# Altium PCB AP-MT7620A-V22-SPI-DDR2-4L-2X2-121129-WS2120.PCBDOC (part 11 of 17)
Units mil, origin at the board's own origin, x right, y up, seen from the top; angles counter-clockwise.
Board outline 7316 x 4279 mil, 4 copper layers (Top, Inner Layer 2, Inner Layer 3, Bottom), stack 35.4 mil thick; 640 components, 473 nets, 2041 pads, 2358 vias.
Unrouted connection lines stored in the file: 11.
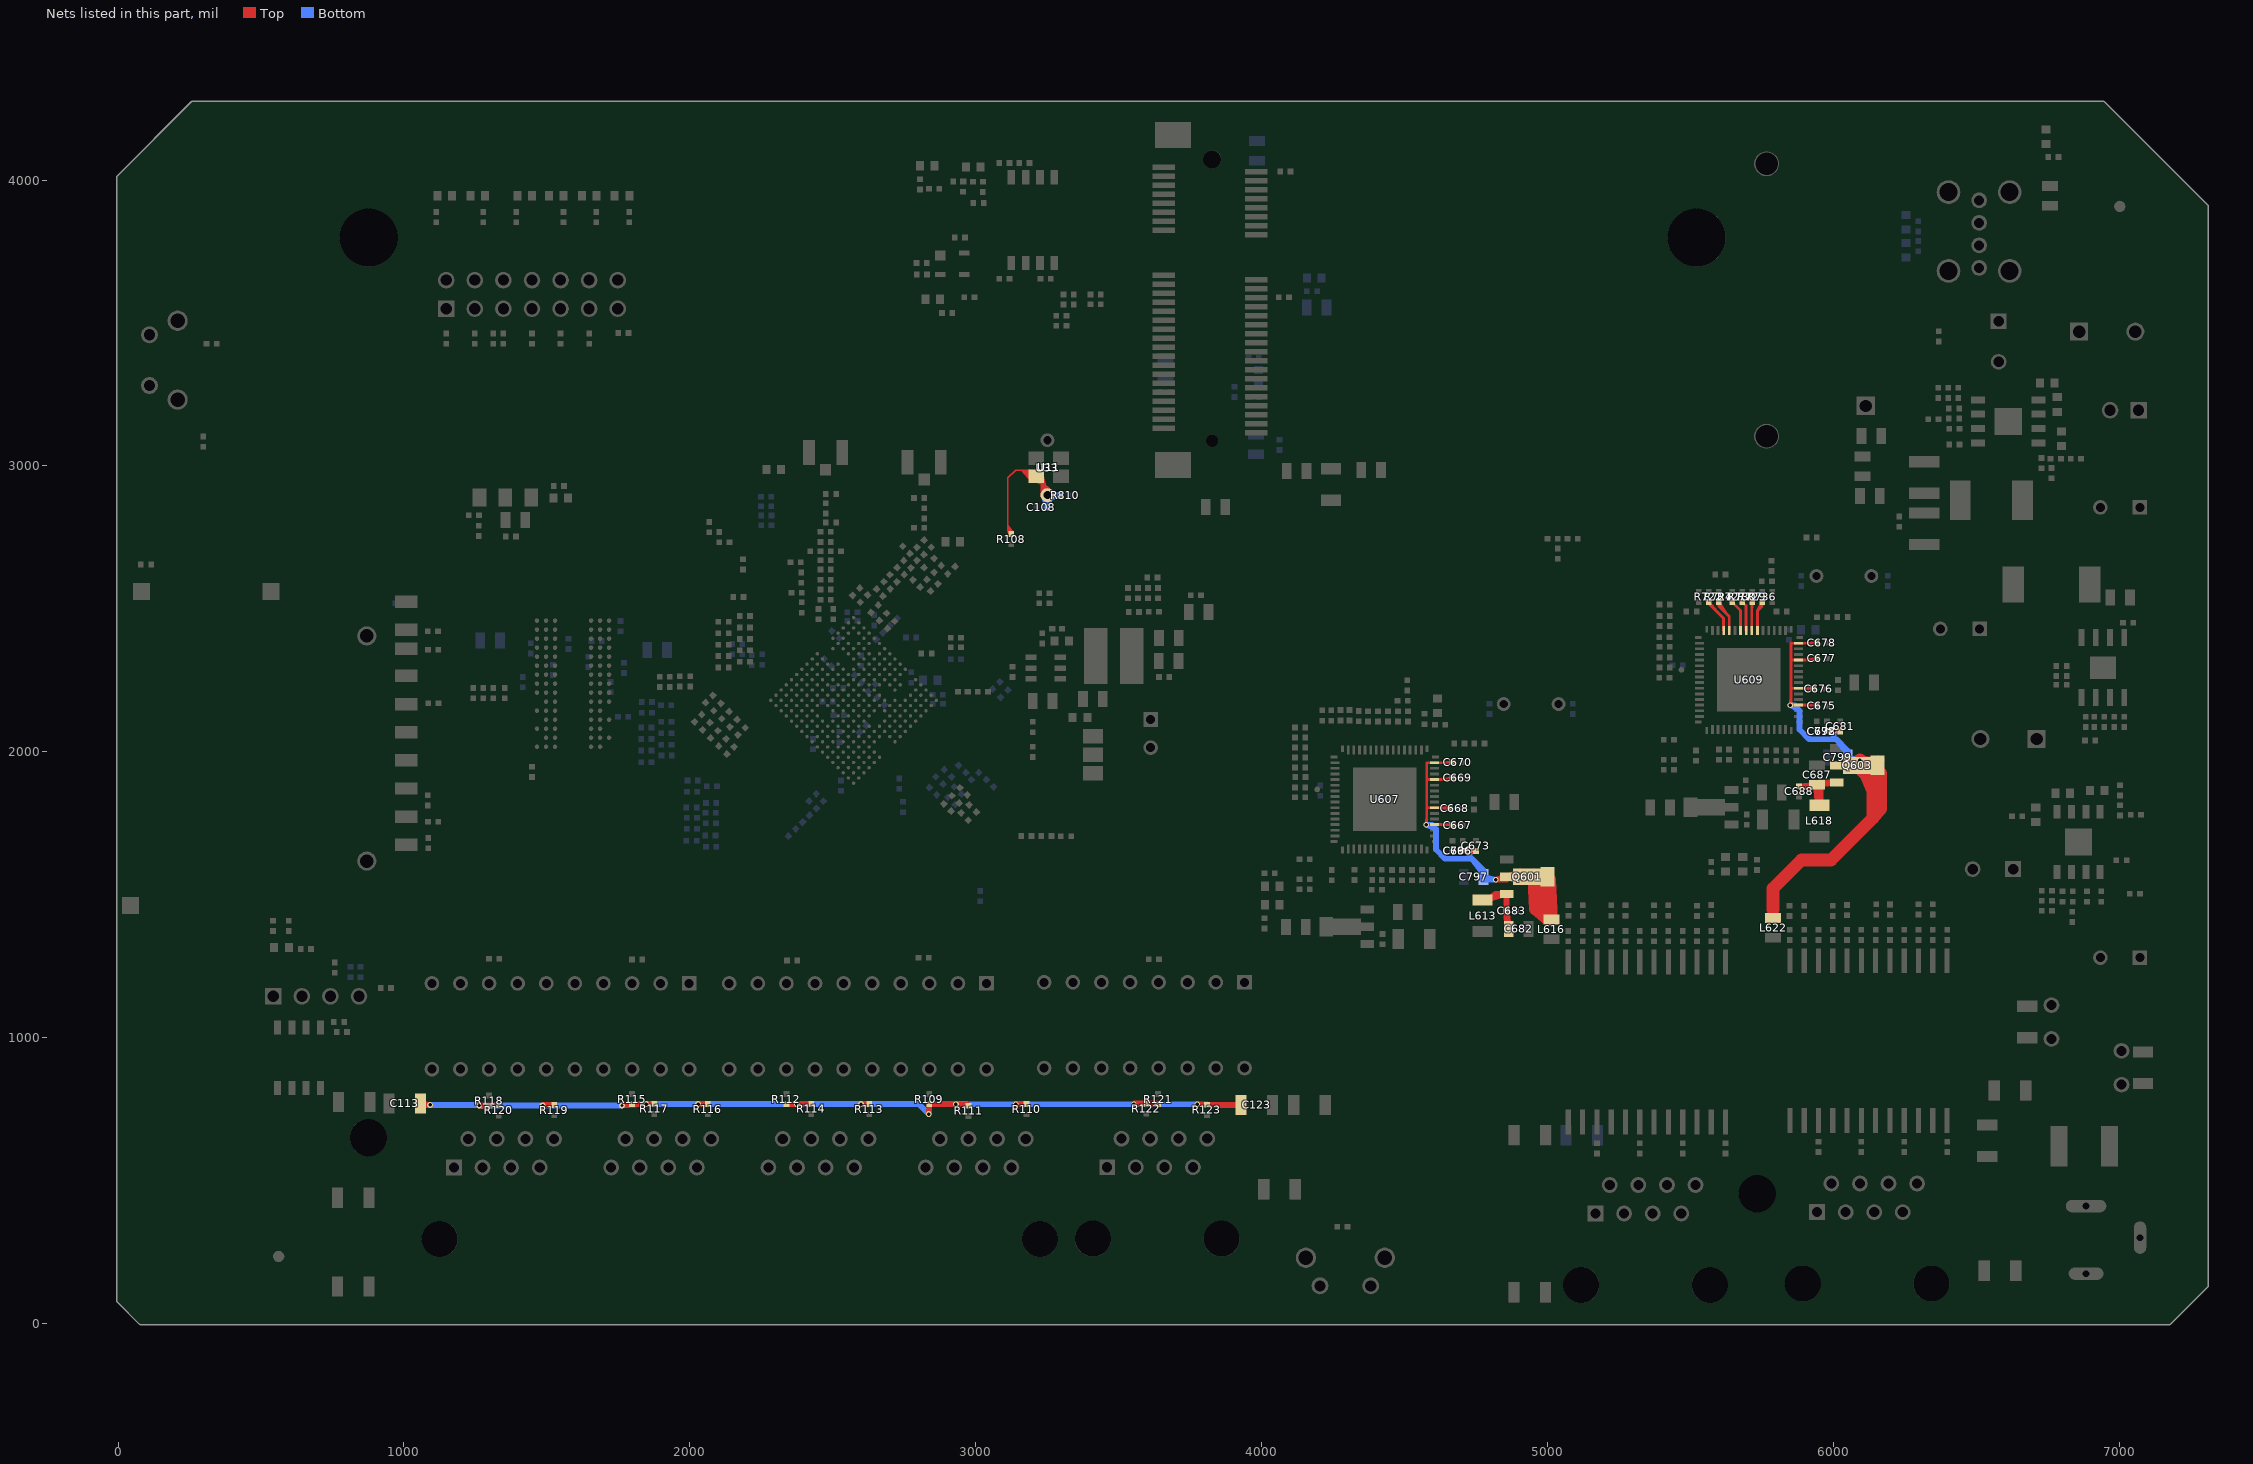
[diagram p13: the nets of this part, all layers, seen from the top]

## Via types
v1: diameter 20, hole 12, Top to Bottom, 2117 vias
v2: diameter 16, hole 8, Top to Bottom, 241 vias

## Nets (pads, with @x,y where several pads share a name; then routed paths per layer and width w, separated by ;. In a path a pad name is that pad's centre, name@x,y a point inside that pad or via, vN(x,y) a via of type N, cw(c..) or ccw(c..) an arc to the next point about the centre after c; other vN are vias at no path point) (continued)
OSC_O_1-CPU-RT0: C108.1 R108.2 R810.1 U11.1 U33.1 | length 5054.6
  Top w5: R108.2@3116.73,2760.14 3112.5,2791.8 ; R108.2@3130.63,2765.5 3112.5,2791.8 ; U11.1@3195.26,2946.47 3160.59,2985 ; U11.1@3198.87,2950.05 3160.59,2985 ; U11.1@3202.08,2953.94 3160.59,2985 ; U11.1@3203.47,2946.23 3245.92,2929.28 ; U11.1@3204.89,2958.09 3160.59,2985 ; U11.1@3205.63,2950.86 3245.92,2929.28 ; U11.1@3207.76,2963.5 3160.59,2985 ; U11.1@3208.26,2955.17 3245.92,2929.28 ; U11.1@3209.96,2969.21 3160.59,2985 ; U11.1@3211.26,2974.06 3160.59,2985 ; U11.1@3211.33,2959.15 3245.92,2929.28 ; U11.1@3212.08,2979.04 3160.59,2985 ; U11.1@3212.42,2984.11 3160.59,2985 ; U11.1@3215.63,2963.5 3245.92,2929.28 ; U11.1@3220.48,2967.25 3245.92,2929.28 ; U11.1@3224.79,2969.81 3245.92,2929.28 ; U11.1@3229.4,2971.89 3245.92,2929.28 ; U33.1@3229.75,2893.49 U11.1@3230.03,2945.17 ; U11.1@3234.25,2973.47 3245.92,2929.28 ; U33.1@3234.83,2893.71 U11.1@3230.03,2945.17 ; U33.1@3239.83,2894.43 U11.1@3230.03,2945.17 ; U33.1@3244.7,2895.62 U11.1@3230.03,2945.17 ; U33.1@3256.95,2901.05 U11.1@3230.03,2945.17 ; U33.1@3261.1,2903.87 U11.1@3230.03,2945.17 ; U33.1@3264.98,2907.1 U11.1@3230.03,2945.17 ; U33.1@3268.55,2910.72 U11.1@3230.03,2945.17 ; 3112.5,2773.5 3112.5,2958 3139.5,2985 3190.2,2985 U11.1@3211.69,2963.5 3251,2924.2 ; 3112.5,2773.5 R108.2@3124,2762 ; 3112.5,2773.5 3117.62,2758.06 3112.5,2773.5 ; 3112.5,2773.5 3127.94,2768.38 3112.5,2773.5 ; 3112.5,2773.5 R108.2@3124,2762 ; 3112.5,2791.8 R108.2@3124,2762 ; U11.1@3230.03,2945.17 U33.1@3251,2897.94 ; U33.1@3251,2897.94 3251,2924.2 ; U33.1@3251,2897.94 3251,2924.2 ; 3251,2924.2 3231.23,2906.91 3251,2924.2 ; 3251,2924.2 3270.77,2906.91 3251,2924.2 ; 3251,2924.2 3235.16,2903.26 3251,2924.2 ; 3251,2924.2 3266.84,2903.26 3251,2924.2 ; 3251,2924.2 3239.58,2900.55 3251,2924.2 ; 3251,2924.2 3262.42,2900.55 3251,2924.2 ; 3251,2924.2 3244.34,2898.79 3251,2924.2 ; 3251,2924.2 3257.66,2898.79 3251,2924.2
  Bottom w5: U33.1@3229.3,2897.19 C108.1@3241.48,2859.02 ; U33.1@3229.73,2893.56 C108.1@3248,2858.68 ; U33.1@3230.75,2890.1 C108.1@3254.94,2857.67 ; U33.1@3234.29,2898.43 C108.1@3241.48,2859.02 ; U33.1@3234.45,2895.64 C108.1@3248,2858.68 ; U33.1@3235.06,2892.91 C108.1@3254.94,2857.67 ; U33.1@3239.32,2897.08 C108.1@3248,2858.68 ; U33.1@3239.34,2899.03 C108.1@3241.48,2859.02 ; U33.1@3239.63,2895.12 C108.1@3254.94,2857.67 ; C108.1@3240.58,2856.12 3248,2880 C108.1@3255.42,2856.12 ; U33.1@3244.29,2897.88 C108.1@3248,2858.68 ; U33.1@3244.37,2898.98 C108.1@3241.48,2859.02 ; U33.1@3244.4,2896.73 C108.1@3254.94,2857.67 ; C108.1@3248,2855 3248,2894.94 U33.1@3251,2897.94 ; U33.1@3250.34,2891.26 R810.1@3290.78,2890.62 ; U33.1@3250.57,2886.23 R810.1@3290.78,2890.62 ; U33.1@3250.63,2904.64 R810.1@3290.63,2903.5 ; U33.1@3251.09,2909.65 R810.1@3290.63,2903.5 ; U33.1@3251.44,2881.23 R810.1@3290.78,2890.62 ; U33.1@3251.44,2891.24 R810.1@3290.22,2897.18 ; U33.1@3251.57,2891.25 R810.1@3290.21,2897.94 ; U33.1@3251.57,2904.62 R810.1@3290.21,2897.94 ; U33.1@3251.7,2904.61 R810.1@3290.22,2897.18 ; U33.1@3252.18,2914.61 R810.1@3290.63,2903.5 ; U33.1@3252.52,2886.32 R810.1@3290.22,2897.18 ; U33.1@3252.49,2891.39 R810.1@3290.63,2903.5 ; U33.1@3252.75,2886.36 R810.1@3290.21,2897.94 ; U33.1@3252.76,2904.42 R810.1@3290.78,2890.62 ; U33.1@3252.75,2909.52 R810.1@3290.21,2897.94 ; U33.1@3252.95,2876.31 R810.1@3290.78,2890.62 ; U33.1@3252.97,2909.48 R810.1@3290.22,2897.18 ; U33.1@3253.93,2919.45 R810.1@3290.63,2903.5 ; U33.1@3254.24,2881.54 R810.1@3290.22,2897.18 ; U33.1@3254.31,2886.7 R810.1@3290.63,2903.5 ; U33.1@3254.56,2881.61 R810.1@3290.21,2897.94 ; U33.1@3254.56,2914.27 R810.1@3290.21,2897.94 ; U33.1@3254.76,2909.03 R810.1@3290.78,2890.62 ; U33.1@3254.87,2914.19 R810.1@3290.22,2897.18 ; U33.1@3256.6,2876.96 R810.1@3290.22,2897.18 ; U33.1@3256.73,2882.24 R810.1@3290.63,2903.5 ; U33.1@3257.01,2877.07 R810.1@3290.21,2897.94 ; U33.1@3257.01,2918.8 R810.1@3290.21,2897.94 ; U33.1@3257.36,2895.8 C108.1@3241.48,2859.02 ; U33.1@3257.35,2913.4 R810.1@3290.78,2890.62 ; U33.1@3257.41,2918.68 R810.1@3290.22,2897.18 ; U33.1@3257.63,2896.86 C108.1@3248,2858.68 ; U33.1@3257.71,2898.03 C108.1@3254.94,2857.67 ; U33.1@3259.74,2878.06 R810.1@3290.63,2903.5 ; U33.1@3260.51,2917.45 R810.1@3290.78,2890.62 ; U33.1@3261.85,2893.52 C108.1@3241.48,2859.02 ; U33.1@3262.42,2895.32 C108.1@3248,2858.68 ; U33.1@3262.7,2897.38 C108.1@3254.94,2857.67 ; U33.1@3266.05,2890.67 C108.1@3241.48,2859.02 ; U33.1@3267.01,2893.16 C108.1@3248,2858.68 ; U33.1@3267.61,2896.09 C108.1@3254.94,2857.67 ; U33.1@3269.9,2887.26 C108.1@3241.48,2859.02 ; U33.1@3271.35,2890.38 C108.1@3248,2858.68 ; U33.1@3272.38,2894.17 C108.1@3254.94,2857.67 ; R810.1@3293.6,2889.63 U33.1@3269.98,2897.94 ; R810.1@3294.16,2904.45 U33.1@3269.98,2897.94 ; C108.1@3241.48,2859.02 U33.1@3251,2897.94 ; C108.1@3248,2858.68 U33.1@3251,2897.94 ; U33.1@3251,2897.94 3296,2897.94 3296,2897 R810.1@3295,2897 U33.1@3269.98,2897.94 ; U33.1@3251,2897.94 C108.1@3254.94,2857.67 ; U33.1@3251,2897.94 R810.1@3290.78,2890.62 ; U33.1@3251,2897.94 R810.1@3290.22,2897.18 ; U33.1@3251,2897.94 R810.1@3290.63,2903.5
P1_4-ETHERNET: C113.1 C123.1 R109.1 R110.2 R111.2 R112.1 R113.2 R114.2 R115.1 R116.2 R117.2 R118.1 R119.2 R120.2 R121.1 R122.2 R123.2 | length 5980
  Top w20: 1775.62,763.86 v1(1848,768) ; 1776,768 v1(1848,768) ; 1836.21,768 v1(1763,763) ; 2858.97,768 v1(2931,767) ; 2908.04,768 R109.1@2838,767 ; R123.2@3809,765 C123.1@3927.88,765 3848.2,765 ; 3879.04,765 R123.2@3809,766 ; C113.1@1058.12,770 C113.1@1063.12,765 ; C113.1@1058.12,770 v1(1091.5,765) ; C113.1@1058.12,770 v1(1091.5,765) ; C113.1@1063.12,765 v1(1091.5,765) ; C113.1@1063.12,765 v1(1091.5,765) ; R118.1@1298,762 1297,763 v1(1264,763) R118.1@1298,762 ; R118.1@1298,762 R118.1@1300,764 ; R118.1@1298,762 R120.2@1332,764 ; R118.1@1298,762 R120.2@1332,764 ; R118.1@1300,764 R120.2@1332,764 ; R118.1@1300,764 R120.2@1332,764 ; v1(1485,763) v1@1487,765 ; v1(1485,763) R119.2@1526,765 ; v1(1485,763) R119.2@1526,765 ; v1@1487,765 R119.2@1526,765 ; v1@1487,765 R119.2@1526,765 ; v1(1763,763) v1@1768,768 ; v1(1763,763) R115.1@1798,767 ; v1@1768,768 v1(1848,768) ; v1@1768,768 R115.1@1798,767 ; R115.1@1798,767 v1(1848,768) ; R115.1@1798,767 v1(1848,768) ; v1(1848,768) v1@1849,769 ; v1(1848,768) R117.2@1876,769 ; v1(1848,768) R117.2@1876,769 ; v1@1849,769 R117.2@1876,769 ; v1@1849,769 R117.2@1876,769 ; R112.1@2338,767 R112.1@2339,768 ; R112.1@2338,767 v1(2374,768) ; R112.1@2338,767 v1(2374,768) ; R112.1@2339,768 v1(2374,768) ; R112.1@2339,768 v1(2374,768) ; v1(2374,768) v1@2375,769 ; v1(2374,768) R114.2@2425,769 ; v1(2374,768) R114.2@2425,769 ; v1@2375,769 R114.2@2425,769 ; v1@2375,769 R114.2@2425,769 ; v1(2836,733) v1@2838,733 ; v1(2836,733) R109.1@2838,767 ; v1(2836,733) R109.1@2838,767 ; v1@2838,733 R109.1@2838,767 ; v1@2838,733 R109.1@2838,767 ; R109.1@2838,767 2838,768 2930,768 v1(2931,767) ; v1(2931,767) 2970,767 R111.2@2975,762 v1(2931,767) ; v1(3140,767) v1@3141,768 ; v1(3140,767) R110.2@3178,768 ; v1(3140,767) R110.2@3178,768 ; v1@3141,768 R110.2@3178,768 ; v1@3141,768 R110.2@3178,768 ; v1(3553,767) v1@3556,770 ; v1(3553,767) R122.2@3597,770 ; v1(3553,767) R122.2@3597,770 ; v1@3556,770 R122.2@3597,770 ; v1@3556,770 R122.2@3597,770 ; R122.2@3597,770 3635,770 R121.1@3638,767 R122.2@3597,770 ; R123.2@3809,766 3808,767 v1(3775,767) R123.2@3809,766 ; v1(2029,768) R116.2@2063,768 v1(2029,768) ; v1(2599,768) R113.2@2628,768 v1(2599,768)
  Bottom w20: v1(1091.5,765) 1262,765 v1(1264,763) ; 1191.83,765 v1(1264,763) ; 1413,763 v1(1485,763) ; 1691,763 v1(1763,763) v1(1485,763) ; v1(1848,768) v1(2029,768) ; 1957,768 v1(2029,768) ; 2302,768 v1(2374,768) ; 2527,768 v1(2599,768) ; v1(2931,767) v1(3140,767) ; 3068,767 v1(3140,767) ; 3481,767 v1(3553,767) ; 3703,767 v1(3775,767) v1(3553,767) ; v1(1264,763) v1(1485,763) ; v1(2029,768) v1(2374,768) ; v1(2374,768) v1(2599,768) ; v1(2599,768) 2801,768 ; 2801,768 v1(2836,733) 2801,768 ; v1(3140,767) v1(3553,767)
P2_RXCLK_1-CPU-RT0: R736.2 U609.39 | length 205.7
  Top w10: U609.39@5734.52,2425.28 5734.52,2493.05 ; U609.39@5734.52,2436.11 5734.52,2471.03 ; R736.2@5750.99,2525.05 R736.2@5750.99,2524.05 ; 5734.52,2493.05 5750.99,2509.52 ; 5734.52,2493.05 R736.2@5750.99,2524.05 ; 5750.99,2509.52 R736.2@5750.99,2524.05 ; 5750.99,2509.52 R736.2@5750.99,2524.05 ; 5750.99,2509.52 R736.2@5750.99,2524.05
P2_RXD0_1-CPU-RT0: R730.2 U609.41 | length 139.6
  Top w10: R730.2@5680.99,2524.05 5695.15,2509.89 U609.41@5695.15,2425.28 ; U609.41@5695.15,2436.11 5695.15,2471.03
P2_RXD1_1-CPU-RT0: R727.2 U609.42 | length 145.9
  Top w10: R727.2@5645.99,2524.05 5675.46,2494.58 U609.42@5675.46,2425.28 ; U609.42@5675.46,2436.11 5675.46,2471.03
P2_RXD2_1-CPU-RT0: R724.2 U609.44 | length 223.2
  Top w10: 5625.85,2484.19 R724.2@5598.99,2524.05 ; U609.44@5636.09,2425.28 5636.09,2473.95 5599,2511.04 ; U609.44@5636.09,2436.11 5636.09,2471.03 ; 5599,2511.04 R724.2@5598.99,2524.05 ; 5599,2511.04 R724.2@5598.99,2524.05 ; 5599,2511.04 R724.2@5598.99,2524.05
P2_RXD3_1-CPU-RT0: R722.2 U609.45 | length 195.5
  Top w10: 5592.75,2490.71 R722.2@5563.99,2524.05 5564,2519.46 5616.41,2467.05 ; U609.45@5616.41,2425.28 5616.41,2467.05 ; U609.45@5616.41,2436.11 5616.41,2467.05
P2_RXDV_1-CPU-RT0: R729.2 U609.40 | length 174.3
  Top w10: U609.40@5714.83,2425.28 5714.83,2522.89 R729.2@5715.99,2524.05 5714.83,2483.99 ; U609.40@5714.83,2436.11 5714.83,2471.03
P_AVDD_IP1001: C666.2 C667.1 C668.1 C669.1 C670.1 C673.1 C796.1 C797.1 L616.1 Q601.2 Q601.4 Q601.5 U607.20 U607.23 U607.28 U607.31 | length 8803.6
  Top w4: Q601.5@4927.5,1563.05 Q601.2@5000.35,1563.05 ; Q601.5@4944.47,1543.98 Q601.2@4991.27,1543.66 ; Q601.5@4944.47,1582.12 Q601.2@4991.27,1582.44 ; Q601.5@4944.62,1539.87 Q601.2@4991.27,1543.66 ; Q601.5@4944.62,1586.23 Q601.2@4991.27,1582.44 ; Q601.5@4944.67,1548.05 Q601.2@4991.27,1543.66 ; Q601.5@4944.67,1578.05 Q601.2@4991.27,1582.44 ; Q601.5@4945.14,1535.75 Q601.2@4991.27,1543.66 ; Q601.5@4945.14,1590.35 Q601.2@4991.27,1582.44 ; Q601.5@4945.23,1552.05 Q601.2@4991.27,1543.66 ; Q601.5@4945.23,1574.05 Q601.2@4991.27,1582.44 ; Q601.5@4946.1,1547.74 Q601.2@4991.36,1547.99 ; Q601.5@4946.1,1578.36 Q601.2@4991.36,1578.11 ; Q601.5@4946.25,1551.78 Q601.2@4991.36,1547.99 ; Q601.5@4946.25,1574.32 Q601.2@4991.36,1578.11 ; Q601.5@4946.3,1543.67 Q601.2@4991.36,1547.99 ; Q601.5@4946.3,1582.43 Q601.2@4991.36,1578.11 ; Q601.5@4946.88,1539.59 Q601.2@4991.36,1547.99 ; Q601.5@4946.88,1586.51 Q601.2@4991.36,1578.11 ; Q601.5@4947.23,1551.61 Q601.2@4991.15,1551.88 ; Q601.5@4947.23,1574.49 Q601.2@4991.15,1574.22 ; Q601.5@4947.44,1547.57 Q601.2@4991.15,1551.88 ; Q601.5@4947.44,1578.53 Q601.2@4991.15,1574.22 ; Q601.5@4947.84,1535.54 Q601.2@4991.36,1547.99 ; Q601.5@4947.84,1590.56 Q601.2@4991.36,1578.11 ; Q601.5@4948.03,1543.53 Q601.2@4991.15,1551.88 ; Q601.5@4948.03,1582.57 Q601.2@4991.15,1574.22 ; Q601.5@4948.16,1551.53 Q601.2@4990.8,1555.38 ; Q601.5@4948.16,1574.57 Q601.2@4990.8,1570.72 ; Q601.5@4948.71,1547.52 Q601.2@4990.8,1555.38 ; Q601.5@4948.71,1578.58 Q601.2@4990.8,1570.72 ; Q601.5@4949.01,1539.52 Q601.2@4991.15,1551.88 ; Q601.5@4949.01,1586.58 Q601.2@4991.15,1574.22 ; Q601.5@4949.03,1551.53 Q601.2@4990.45,1558.56 ; Q601.5@4949.03,1574.57 Q601.2@4990.45,1567.54 ; Q601.5@4949.65,1543.55 Q601.2@4990.8,1555.38 ; Q601.5@4949.65,1582.55 Q601.2@4990.8,1570.72 ; Q601.5@4949.9,1547.57 Q601.2@4990.45,1558.56 ; Q601.5@4949.9,1578.53 Q601.2@4990.45,1567.54 ; Q601.5@4950.27,1551.63 Q601.2@4990.2,1563.05 ; Q601.5@4950.27,1574.47 Q601.2@4990.2,1563.05 ; Q601.5@4950.37,1535.57 Q601.2@4991.15,1551.88 ; Q601.5@4950.37,1590.53 Q601.2@4991.15,1574.22 ; Q601.5@4950.98,1539.64 Q601.2@4990.8,1555.38 ; Q601.5@4950.98,1586.46 Q601.2@4990.8,1570.72 ; Q601.5@4951.16,1543.68 Q601.2@4990.45,1558.56 ; Q601.5@4951.16,1582.42 Q601.2@4990.45,1567.54 ; Q601.5@4951.47,1551.87 Q601.2@4990.45,1567.54 ; Q601.5@4951.47,1574.23 Q601.2@4990.45,1558.56 ; Q601.5@4951.58,1547.8 Q601.2@4990.2,1563.05 ; Q601.5@4951.58,1578.3 Q601.2@4990.2,1563.05 ; Q601.5@4952.25,1552.09 Q601.2@4990.8,1570.72 ; Q601.5@4952.25,1574.01 Q601.2@4990.8,1555.38 ; Q601.5@4952.71,1535.82 Q601.2@4990.8,1555.38 ; Q601.5@4952.71,1590.28 Q601.2@4990.8,1570.72 ; Q601.5@4952.81,1539.89 Q601.2@4990.45,1558.56 ; Q601.5@4952.81,1586.21 Q601.2@4990.45,1567.54 ; Q601.5@4953.04,1552.38 Q601.2@4991.15,1574.22 ; Q601.5@4953.04,1573.72 Q601.2@4991.15,1551.88 ; Q601.5@4953.16,1548.18 Q601.2@4990.45,1567.54 ; Q601.5@4953.16,1577.92 Q601.2@4990.45,1558.56 ; Q601.5@4953.27,1544.07 Q601.2@4990.2,1563.05 ; Q601.5@4953.27,1582.03 Q601.2@4990.2,1563.05 ; Q601.5@4953.86,1552.76 Q601.2@4991.36,1578.11 ; Q601.5@4953.86,1573.34 Q601.2@4991.36,1547.99 ; Q601.5@4954.18,1548.53 Q601.2@4990.8,1570.72 ; Q601.5@4954.18,1577.57 Q601.2@4990.8,1555.38 ; Q601.5@4954.71,1553.23 Q601.2@4991.27,1582.44 ; Q601.5@4954.71,1572.87 Q601.2@4991.27,1543.66 ; Q601.5@4954.86,1536.23 Q601.2@4990.45,1558.56 ; Q601.5@4954.86,1589.87 Q601.2@4990.45,1567.54 ; Q601.5@4955.22,1544.65 Q601.2@4990.45,1567.54 ; Q601.5@4955.22,1548.97 Q601.2@4991.15,1574.22 ; Q601.5@4955.22,1577.13 Q601.2@4991.15,1551.88 ; Q601.5@4955.22,1581.45 Q601.2@4990.45,1558.56 ; Q601.5@4955.34,1540.49 Q601.2@4990.2,1563.05 ; Q601.5@4955.34,1585.61 Q601.2@4990.2,1563.05 ; Q601.5@4956.28,1549.51 Q601.2@4991.36,1578.11 ; Q601.5@4956.28,1576.59 Q601.2@4991.36,1547.99 ; Q601.5@4956.46,1545.14 Q601.2@4990.8,1570.72 ; Q601.5@4956.46,1580.96 Q601.2@4990.8,1555.38 ; Q601.5@4957.36,1550.18 Q601.2@4991.27,1582.44 ; Q601.5@4957.36,1575.92 Q601.2@4991.27,1543.66 ; Q601.5@4957.64,1541.3 Q601.2@4990.45,1567.54 ; Q601.5@4957.64,1584.8 Q601.2@4990.45,1558.56 ; Q601.5@4957.72,1545.74 Q601.2@4991.15,1574.22 ; Q601.5@4957.72,1580.36 Q601.2@4991.15,1551.88 ; Q601.5@4957.8,1537.08 Q601.2@4990.2,1563.05 ; Q601.5@4957.8,1589.02 Q601.2@4990.2,1563.05 ; Q601.5@4958.99,1546.47 Q601.2@4991.36,1578.11 ; Q601.5@4958.99,1579.63 Q601.2@4991.36,1547.99 ; Q601.5@4959.09,1541.95 Q601.2@4990.8,1570.72 ; Q601.5@4959.09,1584.15 Q601.2@4990.8,1555.38 ; Q601.5@4960.3,1547.36 Q601.2@4991.27,1582.44 ; Q601.5@4960.3,1578.74 Q601.2@4991.27,1543.66 ; Q601.5@4960.42,1538.15 Q601.2@4990.45,1567.54 ; Q601.5@4960.42,1587.95 Q601.2@4990.45,1558.56 ; Q601.5@4960.53,1542.73 Q601.2@4991.15,1574.22 ; Q601.5@4960.53,1583.37 Q601.2@4991.15,1551.88 ; Q601.5@4962,1543.66 Q601.2@4991.36,1578.11 ; Q601.5@4962,1582.44 Q601.2@4991.36,1547.99 ; Q601.5@4962.05,1538.99 Q601.2@4990.8,1570.72 ; Q601.5@4962.05,1587.11 Q601.2@4990.8,1555.38 ; Q601.5@4963.49,1544.78 Q601.2@4991.27,1582.44 ; Q601.5@4963.49,1581.32 Q601.2@4991.27,1543.66 ; Q601.5@4963.67,1539.96 Q601.2@4991.15,1574.22 ; Q601.5@4963.67,1586.14 Q601.2@4991.15,1551.88 ; Q601.5@4965.3,1541.11 Q601.2@4991.36,1578.11 ; Q601.5@4965.3,1584.99 Q601.2@4991.36,1547.99 ; Q601.5@4966.95,1542.46 Q601.2@4991.27,1582.44 ; Q601.5@4966.95,1583.64 Q601.2@4991.27,1543.66 ; Q601.2@4993.58,1542 Q601.5@4964.23,1563.05 ; Q601.2@4993.58,1584.1 Q601.5@4964.23,1563.05 ; Q601.2@4995.81,1545.51 Q601.5@4964.23,1563.05 ; Q601.2@4995.81,1580.59 Q601.5@4964.23,1563.05 ; Q601.2@4997.59,1549.21 Q601.5@4964.23,1563.05 ; Q601.2@4997.59,1576.89 Q601.5@4964.23,1563.05 ; Q601.2@4998.93,1553.04 Q601.5@4964.23,1563.05 ; Q601.2@4998.93,1573.06 Q601.5@4964.23,1563.05 ; Q601.2@4999.83,1556.96 Q601.5@4964.23,1563.05 ; Q601.2@4999.83,1569.14 Q601.5@4964.23,1563.05
  Top w4.5: Q601.2@4998.99,1561.69 Q601.2@5007.51,1553.17 ; L616.1@5007.51,1420 L616.1@5014.05,1413.46
  Top w8: U607.23@4604.22,1804.52 4657.48,1804.52 4659,1803 C668.1@4658,1803 4623.92,1804.52 ; U607.23@4615.05,1804.52 4643.97,1804.52 ; C668.1@4657.21,1797.05 4623.92,1804.52 ; C668.1@4657.74,1808.99 4623.92,1804.52
  Top w10: 4577.99,1787.13 v1(4576,1745) ; U607.23@4593.39,1804.52 4577.99,1804.52 ; U607.28@4593.39,1902.95 4577.99,1902.95 ; U607.31@4593.39,1962 4577.99,1962 ; U607.23@4604.22,1804.52 4577.99,1804.52 ; U607.20@4615.05,1745.47 4649.97,1745.47 ; U607.28@4615.05,1902.95 4649.97,1902.95 ; U607.31@4615.05,1962 4649.97,1962 ; 4626.74,1902.95 C669.1@4667.99,1909.05 ; 4627.86,1962 C670.1@4667.99,1964.05 4668.99,1964.05 4668.99,1962 U607.31@4604.22,1962 4577.99,1962 ; 4627.93,1745.47 C667.1@4667.99,1744.05 4668.99,1744.05 4668.99,1745.47 U607.20@4604.22,1745.47 ; v1(4576,1745) v1@4580.99,1745.47 ; v1(4576,1745) 4577.99,1747.05 4577.99,1804.52 ; v1(4576,1745) U607.20@4604.22,1745.47 ; v1(4576,1745) 4593.39,1745.47 v1@4580.99,1745.47 ; 4577.99,1804.52 4577.99,1902.95 ; 4577.99,1902.95 U607.28@4604.22,1902.95 4657.89,1902.95 ; 4577.99,1902.95 4577.99,1962 ; v1@4580.99,1745.47 U607.20@4604.22,1745.47 ; 4657.89,1902.95 4662.99,1908.05 4668.99,1908.05 4668.99,1909.05 C669.1@4667.99,1909.05 ; 4657.89,1902.95 C669.1@4667.99,1909.05 ; 4657.89,1902.95 C669.1@4667.99,1909.05
  Top w20: v1(4727,1654) v1(4727,1654) ; Q601.4@4847.69,1563.05 v1(4818.99,1553.05) 4857.63,1553.05 Q601.4@4857.63,1563.05 ; Q601.5@4904.74,1544.06 Q601.4@4867.57,1563.05 ; Q601.5@4904.74,1582.04 Q601.4@4867.57,1563.05 ; Q601.5@4905.62,1543.87 Q601.4@4857.63,1563.05 ; Q601.5@4905.62,1582.23 Q601.4@4857.63,1563.05 ; Q601.5@4928.99,1563.05 Q601.5@4927.5,1563.05 ; C666.2@4703.99,1654.05 C666.2@4703.99,1654.05 ; C666.2@4703.99,1654.05 v1(4727,1654) ; C666.2@4703.99,1654.05 v1(4727,1654) ; C666.2@4703.99,1654.05 v1(4727,1654) ; C666.2@4703.99,1654.05 v1(4727,1654) ; v1(4727,1654) 4749.04,1654 C673.1@4749.99,1653.05 v1(4727,1654) ; Q601.4@4857.63,1563.05 Q601.5@4927.5,1563.05 ; Q601.4@4857.63,1563.05 4909.3,1563.05 Q601.4@4867.57,1563.05 ; Q601.4@4867.57,1563.05 Q601.5@4927.5,1563.05
  Top w40: Q601.2@4998.99,1561.69 Q601.2@5000.35,1563.05
  Top w45: Q601.2@5000.35,1552.72 L616.1@5007.51,1420 ; Q601.2@5000.35,1552.72 4948.68,1563.05 L616.1@5007.51,1420 ; Q601.2@5000.35,1552.72 L616.1@5014.05,1413.46 5007.51,1553.17 L616.1@5007.51,1420 ; Q601.5@4952.17,1554.56 5003.05,1413.46 4958,1450 Q601.5@4952.17,1554.56
  Bottom w20: C797.1@4776.44,1574.05 4735.99,1626.05 ; v1(4576,1745) 4595,1744.99 ; v1(4576,1745) 4609.99,1730 ; v1(4576,1745) 4595,1744.99 ; 4595,1744.99 4609.99,1730 ; 4609.99,1730 4609.99,1658.05 4641.99,1626.05 4727,1626.05 ; 4727,1626.05 v1(4727,1654) ; 4727,1626.05 4735.99,1626.05 ; 4727,1626.05 v1(4727,1654) ; v1(4727,1654) 4702.99,1654.05 v1(4727,1654) ; v1(4727,1654) C796.1@4703.99,1654.05 v1(4727,1654) ; 4735.99,1626.05 4776.99,1585.05 4776.99,1563.05 C797.1@4776.44,1563.05 ; C797.1@4776.44,1563.05 4770.99,1553.05 v1(4818.99,1553.05) C797.1@4776.44,1563.05
P_AVDD_IP1001-2: C672.2 C675.1 C676.1 C677.1 C678.1 C681.1 C798.1 C799.1 L622.1 Q603.2 Q603.4 Q603.5 U609.20 U609.23 U609.28 U609.31 | length 6503.4
  Top w8: U609.23@5878.22,2222.52 5930.48,2222.52 5932,2221 C676.1@5931,2221 ; U609.23@5889.05,2222.52 5917.97,2222.52 ; C676.1@5928.96,2215.36 5917.97,2222.52 ; C676.1@5930.32,2226.96 5917.97,2222.52 ; 5896.92,2222.52 5930.21,2215.05 5896.93,2222.52 ; 5896.92,2222.52 5930.74,2226.99 5896.93,2222.52 ; 5896.92,2222.52 C676.1@5931,2221 ; 5896.93,2222.52 C676.1@5931,2221 ; 5917.97,2222.52 C676.1@5931,2221
  Top w10: 5851.99,2205.11 v1(5850,2163) ; U609.23@5867.39,2222.52 5851.99,2222.52 ; U609.28@5867.39,2320.95 5851.99,2320.95 ; U609.31@5867.39,2380 5851.99,2380 ; U609.23@5878.22,2222.52 5851.99,2222.52 ; U609.20@5889.05,2163.47 5923.97,2163.47 ; U609.28@5889.05,2320.95 5923.97,2320.95 ; U609.31@5889.05,2380 5923.97,2380 ; 5900.74,2320.95 C677.1@5941.99,2327.05 ; 5901.86,2380 C678.1@5941.99,2382.05 5942.99,2382.05 5942.99,2380 U609.31@5878.22,2380 5851.99,2380 ; 5901.91,2163.47 C675.1@5941.99,2162.05 5940.57,2163.47 U609.20@5878.22,2163.47 ; v1(5850,2163) v1@5853,2163.47 ; v1(5850,2163) 5851.99,2164 5851.99,2222.52 ; v1(5850,2163) U609.20@5878.22,2163.47 ; v1(5850,2163) 5867.39,2163.47 v1@5853,2163.47 ; 5851.99,2222.52 5851.99,2320.95 ; 5851.99,2320.95 U609.28@5878.22,2320.95 5931.89,2320.95 ; 5851.99,2320.95 5851.99,2380 ; v1@5853,2163.47 U609.20@5878.22,2163.47 ; 5931.89,2320.95 5936.99,2326.05 5942.99,2326.05 5942.99,2327.05 C677.1@5941.99,2327.05 ; 5931.89,2320.95 C677.1@5941.99,2327.05 ; 5931.89,2320.95 C677.1@5941.99,2327.05
  Top w18: C672.2@5977.99,2072.05 C672.2@5977.99,2072.05 ; C672.2@5977.99,2072.05 v1(6001,2072) ; C672.2@5977.99,2072.05 v1(6001,2072) ; C672.2@5977.99,2072.05 v1(6001,2072) ; C672.2@5977.99,2072.05 v1(6001,2072) ; v1(6001,2072) 6023.04,2072 C681.1@6023.99,2071.05 v1(6001,2072)
  Top w20: L622.1@5789.05,1418.46 5789.05,1449 ; Q603.5@6097.99,1971.6 Q603.2@6155.06,1977.23 ; Q603.5@6100.71,1972.15 Q603.2@6169.08,1971.05 ; Q603.5@6102.97,1972.31 Q603.2@6154.86,1963.11 ; Q603.5@6105.78,1933.43 Q603.2@6151.49,1949.41 ; Q603.5@6110.5,1934.67 Q603.2@6154.86,1963.11 ; Q603.5@6111.04,1934.9 Q603.2@6169.08,1971.05 ; Q603.5@6114.4,1936.79 Q603.2@6155.06,1977.23 ; Q603.2@6165.12,1971.11 v1(6092.99,1971.05) ; v1(6092.99,1971.05) Q603.2@6169.08,1971.05 ; v1(6092.99,1971.05) Q603.2@6151.49,1949.41 ; v1(6092.99,1971.05) Q603.2@6155.06,1977.23 ; v1(6092.99,1971.05) Q603.2@6154.86,1963.11 ; v1(6092.99,1971.05) Q603.2@6155.06,1977.23 ; v1(6092.99,1971.05) Q603.2@6154.86,1963.11 ; v1(6092.99,1971.05) Q603.2@6151.49,1949.41 ; v1(6092.99,1971.05) 6108.44,1971.59 Q603.2@6151.49,1949.41 ; Q603.5@6103.19,1952.78 Q603.2@6169.08,1971.05 ; Q603.5@6103.19,1952.78 Q603.2@6155.06,1977.23 ; Q603.5@6103.19,1952.78 Q603.2@6154.86,1963.11 ; Q603.5@6103.19,1952.78 Q603.2@6151.49,1949.41
  Top w25: Q603.5@6088.85,1943.6 6138.8,1881.4 ; Q603.5@6089.6,1930.6 6138.8,1881.4 ; Q603.5@6119.15,1958.71 6138.8,1881.4 ; 6133.36,1892.29 v1(6092.99,1971.05) 6103.19,1952.78 6138.8,1881.4
  Top w45: 5789.05,1449 5789.05,1522.25 5888.55,1621.75 5991.75,1621.75 6138.8,1768.8 ; 6150.97,1834.67 v1(6092.99,1971.05) ; Q603.2@6165,1925 6165,1800 ; v1(6092.99,1971.05) Q603.2@6138.8,1938.3 ; v1(6092.99,1971.05) Q603.5@6103.19,1952.78 ; v1(6092.99,1971.05) 6138.8,1881.4 ; v1(6092.99,1971.05) Q603.5@6103.19,1952.78 ; v1(6092.99,1971.05) Q603.2@6138.8,1938.3 ; v1(6092.99,1971.05) Q603.5@6103.19,1952.78 ; v1(6092.99,1971.05) 6123.3,1922.8 ; v1(6092.99,1971.05) Q603.5@6103.19,1952.78 ; v1(6092.99,1971.05) Q603.2@6154.86,1942.45 ; v1(6092.99,1971.05) Q603.5@6103.19,1952.78 ; v1(6092.99,1971.05) 6138.8,1881.4 ; v1(6092.99,1971.05) Q603.5@6103.19,1952.78 ; v1(6092.99,1971.05) Q603.2@6154.86,1942.45 ; v1(6092.99,1971.05) Q603.5@6103.19,1952.78 ; v1(6092.99,1971.05) 6123.3,1922.8 ; v1(6092.99,1971.05) Q603.5@6103.19,1952.78 ; v1(6092.99,1971.05) Q603.2@6154.86,1942.45 ; v1(6092.99,1971.05) Q603.5@6103.19,1952.78 ; v1(6092.99,1971.05) Q603.5@6103.19,1952.78 ; Q603.5@6103.19,1952.78 Q603.2@6138.8,1938.3 ; Q603.5@6103.19,1952.78 6138.8,1881.4 ; Q603.5@6103.19,1952.78 Q603.2@6138.8,1938.3 ; Q603.5@6103.19,1952.78 6123.3,1922.8 ; Q603.5@6103.19,1952.78 Q603.2@6154.86,1942.45 ; Q603.5@6103.19,1952.78 6138.8,1881.4 ; Q603.5@6103.19,1952.78 Q603.2@6154.86,1942.45 ; Q603.5@6103.19,1952.78 6123.3,1922.8 ; Q603.5@6103.19,1952.78 6165,1800 ; Q603.5@6103.19,1952.78 Q603.2@6154.86,1942.45 ; 6123.3,1922.8 Q603.2@6138.8,1938.3 ; 6123.3,1922.8 Q603.2@6154.86,1942.45 ; 6138.8,1768.8 6138.8,1881.4 ; 6138.8,1768.8 6165,1800 ; 6138.8,1881.4 Q603.2@6138.8,1938.3 ; 6138.8,1881.4 Q603.2@6154.86,1942.45 ; Q603.2@6154.86,1942.45 6165,1800
  Bottom w20: C799.1@6050.44,1992.05 6009.99,2044.05 ; v1(5850,2163) 5863,2163 ; v1(5850,2163) 5882,2144 ; v1(5850,2163) 5863,2163 ; 5863,2163 5882,2144 ; 5882,2144 5882,2078.04 5915.99,2044.05 6001,2044.05 ; 6001,2044.05 6009.99,2044.05 ; 6001,2044.05 v1(6001,2072) ; 6001,2044.05 v1(6001,2072) ; v1(6001,2072) 5976.99,2072.05 v1(6001,2072) ; v1(6001,2072) C798.1@5977.99,2072.05 v1(6001,2072) ; 6009.99,2044.05 6050.99,2003.05 6050.99,1981.05 C799.1@6050.44,1981.05 ; C799.1@6050.44,1981.05 6044.99,1971.05 v1(6092.99,1971.05) C799.1@6050.44,1981.05
P_AVDDH_IP1001: C682.1 C683.1 L613.2 Q601.3 | length 1004.4
  Top w20: L613.2@4772.99,1482.17 4773.11,1482.05 4796.83,1482.05 4817.99,1503.21 ; C682.1@4864.54,1381.05 C682.1@4857.99,1381.05 ; Q601.3@4865.49,1503.21 Q601.3@4856.99,1503.21 ; L613.2@4788.74,1482.17 4817.99,1503.21 ; L613.2@4788.74,1482.17 Q601.3@4847.69,1503.21 ; L613.2@4788.74,1482.17 4817.99,1503.21 ; L613.2@4788.74,1482.17 Q601.3@4847.69,1503.21 ; L613.2@4788.74,1482.17 4817.99,1503.21 ; L613.2@4788.74,1482.17 Q601.3@4856.99,1503.21 ; L613.2@4788.74,1482.17 4817.99,1503.21 ; L613.2@4788.74,1482.17 Q601.3@4857.63,1503.21 ; L613.2@4788.74,1482.17 4817.99,1503.21 ; 4817.99,1503.21 Q601.3@4856.99,1503.21 ; 4817.99,1503.21 Q601.3@4857.63,1503.21 ; 4817.99,1503.21 Q601.3@4847.69,1503.21 ; 4817.99,1503.21 Q601.3@4847.69,1503.21 ; C683.1@4856.99,1444.05 C683.1@4857.99,1443.05 ; C683.1@4856.99,1444.05 Q601.3@4856.99,1503.21 ; C683.1@4856.99,1444.05 Q601.3@4857.63,1503.21 ; C683.1@4856.99,1444.05 C682.1@4857.99,1381.05 ; C683.1@4856.99,1444.05 4864.54,1392.05 C683.1@4857.99,1443.05 ; C682.1@4857.99,1381.05 C683.1@4857.99,1443.05
P_AVDDH_IP1001-2: C687.1 C688.1 L618.2 Q603.3 | length 592.8
  Top w20: C687.1@5943,1884.55 C687.1@5951.39,1892.94 ; C687.1@5951.39,1892.94 Q603.3@6012.14,1892.94 5954,1884.55 6002.2,1892.94 C687.1@5951.39,1892.94 ; C688.1@5880,1879 5935.5,1879 C688.1@5880,1880 5932,1884.55 C688.1@5880,1879
  Top w30: C687.1@5943,1884.55 5951.24,1876.31 L618.2@5951.24,1813.4 C687.1@5943,1884.55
